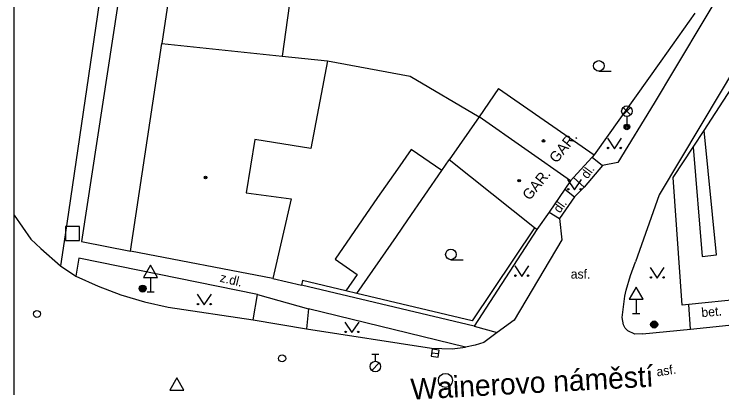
# Model space of a CAD drawing. Extents: x -596024 to -594475, y -1163820 to -1161957.
# Drawn here: x -596024.4 to -595974.1, y -1163003 to -1162976.4 of the extents above; entities that cross this region are included whole.
import ezdxf

# ---------------------------------------------------------------- set-up
doc = ezdxf.new("R2010")
doc.units = 0
for name, color, linetype in [('Level 10', 7, 'Continuous'), ('Level 11', 7, 'Continuous'), ('Level 25', 7, 'Continuous'), ('Level 26', 7, 'Continuous'), ('Level 27', 7, 'Continuous'), ('Level 28', 7, 'Continuous'), ('Level 33', 7, 'Continuous'), ('Level 34', 7, 'Continuous'), ('Level 36', 7, 'Continuous'), ('Level 39', 7, 'Continuous'), ('Level 40', 7, 'Continuous'), ('Level 41', 7, 'Continuous'), ('Level 5', 7, 'Continuous'), ('Level 50', 7, 'Continuous'), ('Level 7', 7, 'Continuous'), ('Level 8', 7, 'Continuous'), ('Vrstva 63', 7, 'Continuous')]:
    doc.layers.add(name, color=color, linetype=linetype)

msp = doc.modelspace()

# ---------------------------------------------------------------- linework, layer by layer
at = {"layer": 'Level 10'}
for points in [[(-595964.04, -1162966.29), (-595969.95, -1162974.8), (-595974.2, -1162981.91), (-595978.59, -1162989.27), (-595980.28, -1162994.05)], [(-595972.91, -1162972.65), (-595977.51, -1162980.35), (-595978.95, -1162982.76)], [(-595978.95, -1162982.76), (-595981.54, -1162986.99), (-595982.62, -1162987.19)], [(-595982.62, -1162987.19), (-595983.92, -1162988.73)], [(-595983.92, -1162988.73), (-595984.6, -1162989.42)], [(-595984.6, -1162989.42), (-595985.68, -1162990.96)], [(-596024.42, -1162990.728), (-596023.23, -1162992.44), (-596022.52, -1162993.08), (-596021.12, -1162994.33)], [(-595985.68, -1162990.96), (-595985.5, -1162992.48), (-595988.9, -1162998.18)], [(-595979.78, -1162999.16), (-595980.32, -1162999.18), (-595980.81, -1162998.95), (-595981.01, -1162998.74), (-595981.13, -1162998.52), (-595981.22, -1162997.99), (-595981.03, -1162996.48), (-595980.94, -1162996.05), (-595980.64, -1162995), (-595980.28, -1162994.05)], [(-596021.12, -1162994.33), (-596020.04, -1162995.05)], [(-596020.04, -1162995.05), (-596018.46, -1162995.77), (-596016.83, -1162996.38), (-596015.17, -1162996.87), (-596013.48, -1162997.26)], [(-596013.48, -1162997.26), (-596007.45, -1162998.16)], [(-596007.45, -1162998.16), (-596003.66, -1162998.8)], [(-595988.9, -1162998.18), (-595990.1, -1162999.06)], [(-595976.38, -1162998.81), (-595972.51, -1162998.42)], [(-596003.66, -1162998.8), (-595994.76, -1163000.16), (-595993.3, -1163000.21), (-595992.35, -1163000.1)], [(-595990.1, -1162999.06), (-595991.04, -1162999.78), (-595991.67, -1162999.96), (-595992.35, -1163000.1)], [(-595979.78, -1162999.16), (-595976.38, -1162998.81)]]:
    msp.add_lwpolyline(points, dxfattribs=at)
at = {"layer": 'Level 11'}
for points in [[(-596015.95, -1162968.45), (-596019.64, -1162992.6), (-596016.16, -1162993.27)], [(-596017.47, -1162969.51), (-596020.8, -1162992.12), (-596021.12, -1162994.33)], [(-596002.15, -1162979.77), (-595996.28, -1162980.85), (-595991.39, -1162983.74)], [(-595976.18, -1162985.89), (-595975.53, -1162993.66), (-595974.53, -1162993.55), (-595975.41, -1162984.71)], [(-595994.04, -1162987.56), (-595996.22, -1162986.07), (-595997.18, -1162987.45), (-595998.6, -1162989.48), (-596001.62, -1162993.86), (-596000.06, -1162994.93), (-596000.86, -1162996.09)], [(-595983.36, -1162986.6), (-595982.62, -1162987.19)], [(-595994.04, -1162987.56), (-595993.51, -1162986.8)], [(-596000.07, -1162996.28), (-595997.26, -1162992.23), (-595996.45, -1162991.06), (-595994.04, -1162987.56)], [(-595984.68, -1162988.05), (-595983.92, -1162988.73)], [(-595985.29, -1162988.87), (-595984.6, -1162989.42)], [(-595986.42, -1162990.5), (-595985.68, -1162990.96)], [(-596007.13, -1162996.36), (-596019.82, -1162993.78), (-596020.04, -1162995.05)], [(-596007.45, -1162998.16), (-596007.13, -1162996.36)], [(-596007.13, -1162996.36), (-596003.5, -1162997.37)], [(-595976.38, -1162998.81), (-595976.48, -1162997.06)], [(-596003.5, -1162997.37), (-596003.66, -1162998.8)], [(-595992.35, -1163000.1), (-596003.5, -1162997.37)], [(-595991.74, -1162998.62), (-595990.1, -1162999.06)]]:
    msp.add_lwpolyline(points, dxfattribs=at)
at = {"layer": 'Level 25'}
for centre, radius in [((-596015.29, -1162995.94), 0.25), ((-596015.29, -1162995.94), 0.2), ((-596015.29, -1162995.94), 0.15), ((-596015.29, -1162995.94), 0.1), ((-596015.29, -1162995.94), 0.05), ((-595978.95, -1162998.49), 0.25), ((-595978.95, -1162998.49), 0.2), ((-595978.95, -1162998.49), 0.15), ((-595978.95, -1162998.49), 0.1), ((-595978.95, -1162998.49), 0.05)]:
    msp.add_circle(centre, radius, dxfattribs=at)
at = {"layer": 'Level 26'}
msp.add_lwpolyline([(-596020.78, -1162992.53), (-596019.78, -1162992.53), (-596019.78, -1162991.53), (-596020.78, -1162991.53)], close=True, dxfattribs=at)
at = {"layer": 'Level 27'}
msp.add_line((-595994.758, -1163000.501), (-595994.262, -1163000.559), dxfattribs=at)
msp.add_lwpolyline([(-595994.787, -1163000.749), (-595994.291, -1163000.807), (-595994.233, -1163000.311), (-595994.729, -1163000.253)], close=True, dxfattribs=at)
msp.add_circle((-595993.78, -1163002.46), 0.5, dxfattribs=at)
at = {"layer": 'Level 28'}
for p, q in [((-595999.01, -1163000.605), (-595998.51, -1163000.605)), ((-595998.76, -1163001.105), (-595998.76, -1163000.605)), ((-595999.018, -1163001.752), (-595998.488, -1163001.222))]:
    msp.add_line(p, q, dxfattribs=at)
for centre, radius in [((-596022.8, -1162997.74), 0.25), ((-596005.38, -1163000.9), 0.25), ((-595998.76, -1163001.48), 0.375)]:
    msp.add_circle(centre, radius, dxfattribs=at)
at = {"layer": 'Level 33'}
for p, q in [((-595981.155, -1162983.6), (-595980.625, -1162983.07)), ((-595981.155, -1162983.07), (-595980.625, -1162983.6)), ((-595980.89, -1162983.71), (-595980.89, -1162984.46))]:
    msp.add_line(p, q, dxfattribs=at)
for centre, radius in [((-595980.89, -1162983.335), 0.375), ((-595980.89, -1162984.46), 0.2), ((-595980.89, -1162984.46), 0.145), ((-595980.89, -1162984.46), 0.0876)]:
    msp.add_circle(centre, radius, dxfattribs=at)
at = {"layer": 'Level 34'}
for p, q in [((-596014.73, -1162995.142), (-596014.73, -1162996.16)), ((-596014.98, -1162996.16), (-596014.48, -1162996.16)), ((-595980.23, -1162996.702), (-595980.23, -1162997.72)), ((-595980.48, -1162997.72), (-595979.98, -1162997.72))]:
    msp.add_line(p, q, dxfattribs=at)
for points in [[(-596015.23, -1162995.142), (-596014.23, -1162995.142), (-596014.73, -1162994.276)], [(-595980.73, -1162996.702), (-595979.73, -1162996.702), (-595980.23, -1162995.836)], [(-596013.37, -1163003.152), (-596012.37, -1163003.152), (-596012.87, -1163002.286)]]:
    msp.add_lwpolyline(points, close=True, dxfattribs=at)
at = {"layer": 'Level 36'}
for p, q in [((-595982.88, -1162980.495), (-595982.005, -1162980.495)), ((-595993.39, -1162993.885), (-595992.515, -1162993.885))]:
    msp.add_line(p, q, dxfattribs=at)
for points in [[(-595982.27, -1162985.25), (-595981.77, -1162986), (-595981.27, -1162985.25)], [(-595985.11, -1162988.18), (-595984.61, -1162988.93), (-595984.11, -1162988.18)], [(-595988.86, -1162994.32), (-595988.36, -1162995.07), (-595987.86, -1162994.32)], [(-595979.23, -1162994.45), (-595978.73, -1162995.2), (-595978.23, -1162994.45)], [(-596011.41, -1162996.34), (-596010.91, -1162997.09), (-596010.41, -1162996.34)], [(-596000.92, -1162998.32), (-596000.42, -1162999.07), (-595999.92, -1162998.32)]]:
    msp.add_lwpolyline(points, dxfattribs=at)
for centre, radius in [((-595982.88, -1162980.12), 0.375), ((-595982.22, -1162985.95), 0.05), ((-595981.321, -1162985.95), 0.05), ((-595985.06, -1162988.88), 0.05), ((-595984.161, -1162988.88), 0.05), ((-595993.39, -1162993.51), 0.375), ((-595988.81, -1162995.02), 0.05), ((-595987.911, -1162995.02), 0.05), ((-595979.18, -1162995.15), 0.05), ((-595978.281, -1162995.15), 0.05), ((-596011.36, -1162997.04), 0.05), ((-596010.461, -1162997.04), 0.05), ((-596000.87, -1162999.02), 0.05), ((-595999.971, -1162999.02), 0.05)]:
    msp.add_circle(centre, radius, dxfattribs=at)
at = {"layer": 'Level 39'}
for centre, radius in [((-595986.81, -1162985.45), 0.09), ((-595986.81, -1162985.45), 0.0398), ((-596010.82, -1162988.05), 0.09), ((-596010.82, -1162988.05), 0.0398), ((-595988.54, -1162988.27), 0.09), ((-595988.54, -1162988.27), 0.0398)]:
    msp.add_circle(centre, radius, dxfattribs=at)
at = {"layer": 'Level 5'}
for points in [[(-596012.49, -1162968.85), (-596013.93, -1162978.54)], [(-596004.61, -1162973.97), (-596005.37, -1162979.44)], [(-596016.16, -1162993.27), (-596013.93, -1162978.54)], [(-596013.93, -1162978.54), (-596005.37, -1162979.44)], [(-596005.37, -1162979.44), (-596002.15, -1162979.77)], [(-596002.15, -1162979.77), (-596003.35, -1162985.99)], [(-595990, -1162981.72), (-595991.39, -1162983.74)], [(-595990, -1162981.72), (-595983.21, -1162986.43)], [(-595991.39, -1162983.74), (-595993.51, -1162986.8)], [(-595984.89, -1162988.29), (-595991.39, -1162983.74)], [(-596007.33, -1162985.34), (-596007.93, -1162989.14)], [(-596003.35, -1162985.99), (-596007.33, -1162985.34)], [(-595983.36, -1162986.6), (-595984.68, -1162988.05)], [(-595983.21, -1162986.43), (-595983.36, -1162986.6)], [(-595987.45, -1162991.62), (-595993.51, -1162986.8)], [(-595984.68, -1162988.05), (-595984.89, -1162988.29)], [(-595984.89, -1162988.29), (-595985.29, -1162988.87)], [(-595985.29, -1162988.87), (-595986.42, -1162990.5)], [(-596007.93, -1162989.14), (-596004.75, -1162989.57)], [(-596004.75, -1162989.57), (-596006.05, -1162995.22)], [(-595986.42, -1162990.5), (-595987.29, -1162991.75)], [(-595987.29, -1162991.75), (-595987.45, -1162991.62)], [(-596006.05, -1162995.22), (-596016.16, -1162993.27)]]:
    msp.add_lwpolyline(points, dxfattribs=at)
at = {"layer": 'Level 7'}
for points in [[(-595976.05, -1162976.38), (-595978.47, -1162979.78), (-595983.21, -1162986.43)], [(-595976.95, -1162997.11), (-595977.61, -1162988.05), (-595976.18, -1162985.89), (-595975.41, -1162984.71), (-595974.88, -1162983.91), (-595973.73, -1162982.16), (-595973.22, -1162981.38), (-595971.5, -1162978.75)], [(-595987.45, -1162991.62), (-595991.89, -1162998.22), (-596000.07, -1162996.28)], [(-595987.29, -1162991.75), (-595991.74, -1162998.62)], [(-596000.86, -1162996.09), (-596003.93, -1162995.36), (-596004.01, -1162995.7)], [(-595991.74, -1162998.62), (-596004.01, -1162995.7)], [(-596000.07, -1162996.28), (-596000.86, -1162996.09)], [(-595976.48, -1162997.06), (-595976.95, -1162997.11)], [(-595972.78, -1162996.68), (-595976.48, -1162997.06)]]:
    msp.add_lwpolyline(points, dxfattribs=at)
at = {"layer": 'Level 8'}
msp.add_lwpolyline([(-596006.05, -1162995.22), (-596004.01, -1162995.7)], dxfattribs=at)
at = {"layer": 'Vrstva 63'}
msp.add_lwpolyline([(-594475.47, -1163820.23), (-596024.42, -1163820.23), (-596024.42, -1161956.88), (-594475.47, -1161956.88)], close=True, dxfattribs=at)

# ---------------------------------------------------------------- texts
at = {"layer": 'Level 40'}
for s, rotation, p in [('dl.', 54.14, (-595983.69, -1162988.19)), ('dl.', 54.14, (-595985.65, -1162990.62)), ('z.dl.', 346.47, (-596009.85, -1162995.44)), ('bet.', 4.91, (-595975.57, -1162997.97)), ('asf.', 8.38, (-595978.74, -1163002.18))]:
    msp.add_text(s, height=0.65, rotation=rotation, dxfattribs=at).set_placement(p)
msp.add_text('asf.', height=0.65, dxfattribs=at).set_placement((-595984.88, -1162995.23))
at = {"layer": 'Level 41'}
for p in [(-595985.89, -1162987.08), (-595987.8, -1162989.72)]:
    msp.add_text('GAR.', height=0.75, rotation=50.95, dxfattribs=at).set_placement(p)
at = {"layer": 'Level 50'}
msp.add_text('Wainerovo náměstí', height=1.5, rotation=3.108, dxfattribs=at).set_placement((-595996.215, -1163003.835))

doc.saveas('drawing.dxf')
